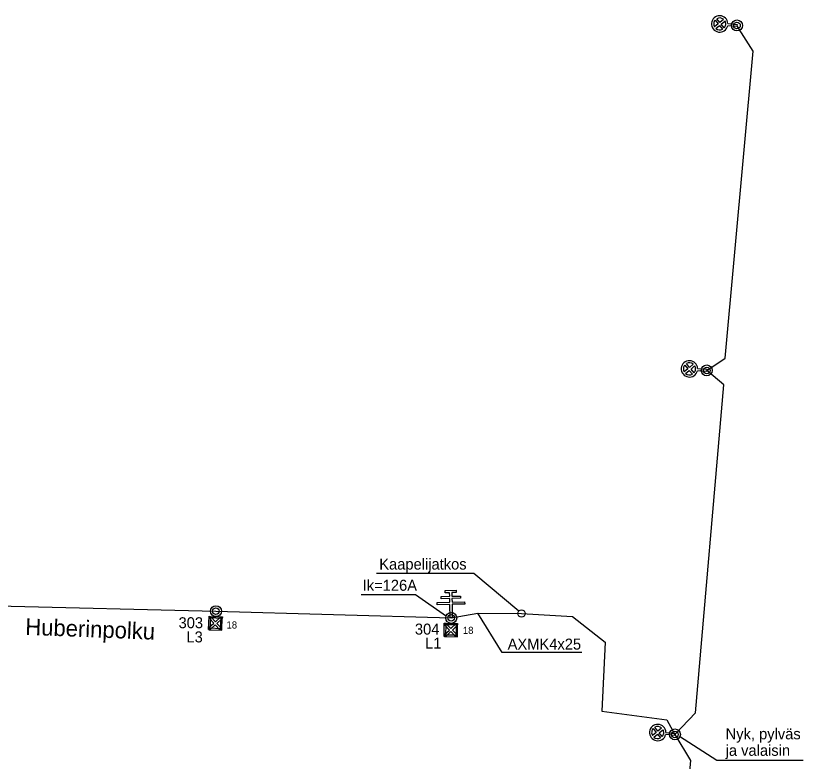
# Model space of a CAD drawing. Extents: x 25497852 to 25498297, y 6686544 to 6687252.
# Drawn here: x 25498168.3 to 25498275.9, y 6687150.6 to 6687252.5 of the extents above; entities that cross this region are included whole.
import ezdxf

# ---------------------------------------------------------------- set-up
doc = ezdxf.new("R2010")
doc.units = 0
for name, color, linetype in [('KayttoOikeusYksikko_piste_tunnus', 7, 'Continuous'), ('KiinteistoNimi', 7, 'Continuous'), ('Rajamerkki_tonttipyykki', 7, 'Continuous'), ('Rasitealue', 7, 'Continuous'), ('Rasiteviiva', 7, 'Continuous'), ('Taso 1', 7, 'Continuous')]:
    doc.layers.add(name, color=color, linetype=linetype)

msp = doc.modelspace()

# ---------------------------------------------------------------- linework, layer by layer
at = {"layer": 'KayttoOikeusYksikko_piste_tunnus'}
for p, q in [((25498263.81, 6687251.88), (25498264.24, 6687251.38)), ((25498264.47, 6687251.57), (25498264.04, 6687252.07)), ((25498264.97, 6687251.99), (25498264.47, 6687251.57)), ((25498264.66, 6687251.34), (25498265.17, 6687251.76)), ((25498264.24, 6687251.38), (25498263.73, 6687250.95)), ((25498263.92, 6687250.72), (25498264.43, 6687251.15)), ((25498264.43, 6687251.15), (25498264.85, 6687250.64)), ((25498265.08, 6687250.83), (25498264.66, 6687251.34)), ((25498266.8, 6687251), (25498265.55, 6687251.11)), ((25498265.57, 6687251.41), (25498266.82, 6687251.3)), ((25498266.82, 6687251.3), (25498266.8, 6687251)), ((25498260.11, 6687204.23), (25498259.6, 6687203.8)), ((25498259.68, 6687204.73), (25498260.11, 6687204.23)), ((25498260.34, 6687204.42), (25498259.91, 6687204.93)), ((25498260.84, 6687204.84), (25498260.34, 6687204.42)), ((25498260.53, 6687204.19), (25498261.03, 6687204.61)), ((25498260.95, 6687203.68), (25498260.53, 6687204.19)), ((25498261.44, 6687204.26), (25498262.69, 6687204.15)), ((25498262.69, 6687204.15), (25498262.66, 6687203.85)), ((25498259.79, 6687203.57), (25498260.3, 6687204)), ((25498260.3, 6687204), (25498260.72, 6687203.49)), ((25498262.66, 6687203.85), (25498261.41, 6687203.96)), ((25498255.35, 6687155.04), (25498255.76, 6687154.52)), ((25498256, 6687154.71), (25498255.59, 6687155.22)), ((25498256.52, 6687155.12), (25498256, 6687154.71)), ((25498256.19, 6687154.47), (25498256.7, 6687154.89)), ((25498255.76, 6687154.52), (25498255.25, 6687154.11)), ((25498255.44, 6687153.87), (25498255.95, 6687154.29)), ((25498255.95, 6687154.29), (25498256.37, 6687153.77)), ((25498256.6, 6687153.96), (25498256.19, 6687154.47)), ((25498258.31, 6687154.08), (25498257.07, 6687154.22)), ((25498257.1, 6687154.52), (25498258.35, 6687154.38)), ((25498258.35, 6687154.38), (25498258.31, 6687154.08))]:
    msp.add_line(p, q, dxfattribs=at)
for points in [[(25498194.88, 6687170.38), (25498194.8, 6687168.56), (25498194.6, 6687168.57), (25498194.68, 6687170.39)], [(25498194.95, 6687170.31), (25498195.56, 6687169.64), (25498196.23, 6687170.25), (25498196.44, 6687170.24), (25498196.43, 6687170.03), (25498195.76, 6687169.42), (25498196.37, 6687168.75), (25498196.36, 6687168.54), (25498196.15, 6687168.55), (25498195.54, 6687169.22), (25498194.87, 6687168.61), (25498194.66, 6687168.62), (25498194.67, 6687168.84), (25498195.34, 6687169.44), (25498194.73, 6687170.11), (25498194.74, 6687170.32)], [(25498196.51, 6687170.3), (25498196.5, 6687170.1), (25498194.73, 6687170.18), (25498194.74, 6687170.38)], [(25498196.42, 6687168.54), (25498196.5, 6687170.24), (25498196.3, 6687170.25), (25498196.22, 6687168.55)], [(25498194.67, 6687168.76), (25498194.66, 6687168.56), (25498196.42, 6687168.48), (25498196.43, 6687168.68)], [(25498227.03, 6687169.43), (25498227.01, 6687167.61), (25498226.81, 6687167.61), (25498226.83, 6687169.43)], [(25498227.1, 6687169.37), (25498227.73, 6687168.72), (25498228.38, 6687169.36), (25498228.59, 6687169.35), (25498228.59, 6687169.14), (25498227.94, 6687168.51), (25498228.58, 6687167.86), (25498228.57, 6687167.65), (25498228.36, 6687167.65), (25498227.73, 6687168.3), (25498227.08, 6687167.67), (25498226.87, 6687167.67), (25498226.87, 6687167.88), (25498227.52, 6687168.51), (25498226.89, 6687169.16), (25498226.89, 6687169.37)], [(25498228.65, 6687169.41), (25498228.65, 6687169.21), (25498226.89, 6687169.23), (25498226.89, 6687169.43)], [(25498228.64, 6687167.65), (25498228.65, 6687169.35), (25498228.45, 6687169.35), (25498228.44, 6687167.65)], [(25498226.87, 6687167.81), (25498226.87, 6687167.61), (25498228.64, 6687167.59), (25498228.64, 6687167.79)]]:
    msp.add_lwpolyline(points, close=True, dxfattribs=at)
for centre, radius, start, end in [((25498264.45, 6687251.36), 1.12, 174.979, 347.3167), ((25498264.45, 6687251.36), 1.12, 2.6413, 174.979), ((25498264.45, 6687251.36), 0.825, 174.979, 209.5033), ((25498264.45, 6687251.36), 0.825, 140.4547, 174.979), ((25498264.45, 6687251.36), 0.825, 50.4547, 119.5033), ((25498264.45, 6687251.36), 0.825, 354.979, 29.5033), ((25498264.45, 6687251.36), 0.825, 230.4547, 299.5033), ((25498264.45, 6687251.36), 0.825, 320.4547, 354.979), ((25498260.32, 6687204.21), 1.12, 2.6413, 174.979), ((25498260.32, 6687204.21), 1.12, 174.979, 347.3167), ((25498260.32, 6687204.21), 0.825, 140.4547, 174.979), ((25498260.32, 6687204.21), 0.825, 174.979, 209.5033), ((25498260.32, 6687204.21), 0.825, 50.4547, 119.5033), ((25498260.32, 6687204.21), 0.825, 320.4547, 354.979), ((25498260.32, 6687204.21), 0.825, 354.979, 29.5033), ((25498260.32, 6687204.21), 0.825, 230.4547, 299.5033), ((25498255.98, 6687154.5), 1.12, 173.6233, 345.9611), ((25498255.98, 6687154.5), 1.12, 1.2856, 173.6233), ((25498255.98, 6687154.5), 0.825, 139.099, 173.6233), ((25498255.98, 6687154.5), 0.825, 49.099, 118.1477), ((25498255.98, 6687154.5), 0.825, 353.6233, 28.1477), ((25498255.98, 6687154.5), 0.825, 173.6233, 208.1477), ((25498255.98, 6687154.5), 0.825, 229.099, 298.1477), ((25498255.98, 6687154.5), 0.825, 319.099, 353.6233)]:
    msp.add_arc(centre, radius, start, end, dxfattribs=at)
at = {"layer": 'KiinteistoNimi'}
for centre, radius in [((25498266.81, 6687251.15), 0.75), ((25498266.81, 6687251.15), 0.45), ((25498262.68, 6687204), 0.75), ((25498262.68, 6687204), 0.45), ((25498195.63, 6687171.09), 0.75), ((25498195.63, 6687171.09), 0.45), ((25498227.77, 6687170.17), 0.75), ((25498227.77, 6687170.17), 0.45), ((25498258.33, 6687154.24), 0.75), ((25498258.33, 6687154.24), 0.45)]:
    msp.add_circle(centre, radius, dxfattribs=at)
at = {"layer": 'Rajamerkki_tonttipyykki'}
for p, q in [((25498226.4, 6687173.1), (25498227.56, 6687173.12)), ((25498226.4, 6687172.8), (25498226.4, 6687173.1)), ((25498226.94, 6687173.91), (25498228.44, 6687173.94)), ((25498226.95, 6687173.61), (25498226.94, 6687173.91)), ((25498227.55, 6687173.62), (25498226.95, 6687173.61)), ((25498227.56, 6687173.12), (25498227.55, 6687173.62)), ((25498228.45, 6687173.64), (25498227.85, 6687173.63)), ((25498227.85, 6687173.63), (25498227.86, 6687173.13)), ((25498227.86, 6687173.13), (25498229.02, 6687173.15)), ((25498228.44, 6687173.94), (25498228.45, 6687173.64)), ((25498229.02, 6687173.15), (25498229.03, 6687172.85)), ((25498225.85, 6687172.28), (25498227.58, 6687172.32)), ((25498225.86, 6687171.98), (25498225.85, 6687172.28)), ((25498227.58, 6687172.02), (25498225.86, 6687171.98)), ((25498227.57, 6687172.82), (25498226.4, 6687172.8)), ((25498227.58, 6687172.32), (25498227.57, 6687172.82)), ((25498227.62, 6687170.17), (25498227.58, 6687172.02)), ((25498229.03, 6687172.85), (25498227.87, 6687172.83)), ((25498227.87, 6687172.83), (25498227.88, 6687172.33)), ((25498227.88, 6687172.33), (25498229.6, 6687172.36)), ((25498229.61, 6687172.06), (25498227.88, 6687172.03)), ((25498227.88, 6687172.03), (25498227.92, 6687170.18)), ((25498229.6, 6687172.36), (25498229.61, 6687172.06)), ((25498227.92, 6687170.18), (25498227.62, 6687170.17))]:
    msp.add_line(p, q, dxfattribs=at)
msp.add_circle((25498237.37, 6687170.78), 0.5, dxfattribs=at)
at = {"layer": 'Rasitealue'}
for p, q in [((25498163.96, 6687171.87), (25498195.63, 6687171.09)), ((25498195.63, 6687171.09), (25498227.77, 6687170.17))]:
    msp.add_line(p, q, dxfattribs=at)
for points in [[(25498262.68, 6687204), (25498265.21, 6687205.67), (25498269.02, 6687247.64), (25498266.81, 6687251.15)], [(25498258.33, 6687154.24), (25498261.13, 6687157.19), (25498265.03, 6687202.01), (25498262.68, 6687204)], [(25498227.77, 6687170.17), (25498231.41, 6687170.82), (25498237.37, 6687170.78)], [(25498237.37, 6687170.78), (25498244.36, 6687170.34), (25498248.8, 6687166.85), (25498248.33, 6687157.43), (25498257.22, 6687156.26), (25498258.33, 6687154.24)], [(25498258.33, 6687154.24), (25498260.46, 6687150.68), (25498256.59, 6687106.94), (25498254.07, 6687104.33)]]:
    msp.add_lwpolyline(points, dxfattribs=at)
at = {"layer": 'Taso 1'}
for points in [[(25498217.58, 6687176.28), (25498230.86, 6687176.28), (25498237.01, 6687171.14)], [(25498215.48, 6687173.37), (25498222.89, 6687173.37), (25498227.13, 6687170.4)], [(25498245.61, 6687165.45), (25498234.74, 6687165.45), (25498231.41, 6687170.82)], [(25498275.87, 6687150.68), (25498264.06, 6687150.68), (25498258.97, 6687153.95)]]:
    msp.add_lwpolyline(points, dxfattribs=at)

# ---------------------------------------------------------------- texts
at = {"layer": 'Rasiteviiva'}
for s, height, p in [('Kaapelijatkos', 1.5, (25498217.94, 6687176.78)), ('Ik=126A', 1.5, (25498215.68, 6687173.88)), ('303', 1.5, (25498190.52, 6687168.76)), ('18', 0.975, (25498197.07, 6687168.72)), ('304', 1.5, (25498222.81, 6687167.89)), ('18', 0.975, (25498229.36, 6687167.98)), ('L3', 1.5, (25498191.6, 6687166.82)), ('L1', 1.5, (25498224.21, 6687165.97)), ('AXMK4x25', 1.5, (25498235.48, 6687165.84)), ('Nyk, pylväs', 1.5, (25498265.26, 6687153.57)), ('ja valaisin', 1.5, (25498265.26, 6687151.32))]:
    msp.add_text(s, height=height, dxfattribs=at).set_placement(p)
msp.add_text('Huberinpolku', height=2.25, rotation=357.849, dxfattribs=at).set_placement((25498169.55, 6687167.86))

doc.saveas('drawing.dxf')
